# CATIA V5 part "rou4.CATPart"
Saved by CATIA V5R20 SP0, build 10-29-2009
Part number: rou4
Bounding box of the stored display mesh (mm): x 290 to 325, y -951 to -919, z 0.01 to 31.99
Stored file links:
  D:\Dropbox\Pack 1 sylvain\mmoreau\mmoreau\mmoreau\fin\rou4.CATPart
  U:\think motion\fin\think motion2.CATProduct
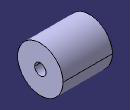
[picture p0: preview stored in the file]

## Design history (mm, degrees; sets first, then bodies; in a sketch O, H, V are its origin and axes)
Set1
  Plane1: linked copy from another document
  Point1: linked copy from another document
Body1 (main body)
  Sketch1 on Plane1, origin (325, 0, 0), H (0, 1, 0), V (0, 0, 1)
    circle A1 centre (-935, 16) radius 16
    point P1 (-935, 16)
    reference projected point E1 (-935, 16) from Point1
    circle A2 centre (-935, 16) radius 4
    point P2 (-935, 16)
    reference projected point E2 (-935, 16) from Point1
    radius A2 = 4
    coincidence: P1 E1, P2 E2
    tangency: A1 H
  Pad1: profile Sketch1, direction (-1, 0, 0), length 35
